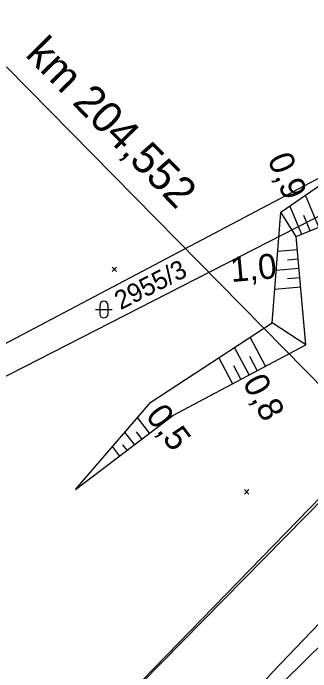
# Model space of a CAD drawing. Extents: x -800194 to -799078, y -1007177 to -1006597.
# Drawn here: x -799466.4 to -799442.5, y -1006906.1 to -1006853.3 of the extents above; entities that cross this region are included whole.
import ezdxf

# ---------------------------------------------------------------- set-up
doc = ezdxf.new("R2010")
doc.units = 0
for name, color, linetype in [('Obvod stavby', 7, 'Continuous'), ('Vrstva 4', 7, 'Continuous'), ('Vrstva 48', 7, 'Continuous'), ('Vrstva 49', 7, 'Continuous'), ('Vrstva 5', 7, 'Continuous'), ('Vrstva 53', 7, 'Continuous'), ('Vrstva 55', 7, 'Continuous'), ('Vrstva 57', 7, 'Continuous'), ('Vrstva 58', 7, 'Continuous')]:
    doc.layers.add(name, color=color, linetype=linetype)

msp = doc.modelspace()

# ---------------------------------------------------------------- linework, layer by layer
at = {"layer": 'Obvod stavby'}
msp.add_lwpolyline([(-799559.64, -1006968.48), (-799519.68, -1006952.01), (-799500.87, -1006940.41), (-799496.64, -1006937.8), (-799494.85, -1006936.7), (-799484.52, -1006930.32), (-799457.99, -1006908.8), (-799435, -1006885.17), (-799430.26, -1006880.27), (-799425.53, -1006875.38), (-799422.55, -1006864.36), (-799416.748, -1006858.798), (-799395.763, -1006879.374), (-799413.75, -1006898.23), (-799418.41, -1006902.53), (-799423.07, -1006906.83), (-799433.4, -1006916.39), (-799469.5, -1006946.86), (-799487.22, -1006958.47), (-799495.25, -1006963.74), (-799521.98, -1006977.8), (-799546.71, -1006987.83)], dxfattribs=at)
at = {"layer": 'Vrstva 4'}
msp.add_lwpolyline([(-799511.236, -1006957.129), (-799499.236, -1006950.771), (-799498.598, -1006949.914), (-799498.679, -1006949.705), (-799496.151, -1006948.479), (-799496.251, -1006948.258), (-799490.687, -1006944.683), (-799490.497, -1006944.878), (-799488.249, -1006943.052), (-799488.105, -1006943.216), (-799486.269, -1006941.68), (-799478.997, -1006936.484), (-799474.568, -1006932.916), (-799474.237, -1006932.694), (-799461.519, -1006921.99), (-799452.935, -1006914.372), (-799444.695, -1006906.886), (-799436.579, -1006898.932), (-799429.629, -1006892.192), (-799429.07, -1006892.727), (-799423.479, -1006886.901), (-799416.56, -1006880.007), (-799417.085, -1006879.46), (-799415.349, -1006878.386)], dxfattribs=at)
at = {"layer": 'Vrstva 48'}
for p, q in [((-799441.897, -1006870.468), (-799442.971, -1006867.903)), ((-799443.28, -1006871.048), (-799444.235, -1006868.768)), ((-799442.588, -1006870.758), (-799443.096, -1006869.547)), ((-799443.626, -1006872.289), (-799445.215, -1006872.43)), ((-799443.56, -1006873.036), (-799444.417, -1006873.112)), ((-799443.494, -1006873.783), (-799445.333, -1006873.946)), ((-799443.427, -1006874.53), (-799444.41, -1006874.617)), ((-799443.361, -1006875.277), (-799445.451, -1006875.463)), ((-799446.183, -1006881.617), (-799447.42, -1006879.29)), ((-799447.507, -1006882.321), (-799448.681, -1006880.114)), ((-799448.832, -1006883.025), (-799449.942, -1006880.937)), ((-799446.845, -1006881.969), (-799447.448, -1006880.835)), ((-799448.169, -1006882.673), (-799448.74, -1006881.599)), ((-799455.512, -1006887.006), (-799456.472, -1006885.742)), ((-799456.707, -1006887.913), (-799457.474, -1006886.903)), ((-799456.11, -1006887.459), (-799456.541, -1006886.891)), ((-799457.902, -1006888.82), (-799458.475, -1006888.065)), ((-799457.304, -1006888.366), (-799457.639, -1006887.925))]:
    msp.add_line(p, q, dxfattribs=at)
at = {"layer": 'Vrstva 49'}
for p, q in [((-799443.72, -1006871.232), (-799444.968, -1006869.269)), ((-799458.508, -1006873.685), (-799458.154, -1006874.039)), ((-799458.508, -1006874.039), (-799458.154, -1006873.685)), ((-799442.951, -1006879.899), (-799445.66, -1006878.142)), ((-799447.872, -1006891.527), (-799447.518, -1006891.881)), ((-799447.872, -1006891.881), (-799447.518, -1006891.527))]:
    msp.add_line(p, q, dxfattribs=at)
for points in [[(-799461.444, -1006891.51), (-799455.403, -1006884.501), (-799445.66, -1006878.142), (-799444.968, -1006869.269), (-799439.353, -1006865.427)], [(-799461.444, -1006891.51), (-799453.63, -1006885.576), (-799442.951, -1006879.899), (-799443.72, -1006871.232), (-799441.503, -1006870.303)], [(-799429.125, -1006891.656), (-799433.133, -1006889.484), (-799437.572, -1006888.963), (-799439.693, -1006890.332), (-799461.15, -1006912.135), (-799487.142, -1006929.222), (-799487.006, -1006931.546), (-799490.308, -1006935.771)], [(-799490.09, -1006944.145), (-799488.194, -1006942.597), (-799488.011, -1006942.815), (-799488.011, -1006942.815), (-799486.419, -1006941.508), (-799486.269, -1006941.68), (-799484.618, -1006939.109), (-799474.926, -1006932.405), (-799474.596, -1006932.171), (-799461.519, -1006921.99), (-799452.935, -1006914.372), (-799445.566, -1006906.106), (-799432.588, -1006892.596), (-799429.125, -1006891.656)]]:
    msp.add_lwpolyline(points, dxfattribs=at)
at = {"layer": 'Vrstva 5'}
msp.add_line((-799466.989, -1006857.616), (-799431.886, -1006893.222), dxfattribs=at)
at = {"layer": 'Vrstva 53'}
msp.add_lwpolyline([(-799559.64, -1006968.48), (-799519.68, -1006952.01), (-799500.87, -1006940.41), (-799496.64, -1006937.8), (-799494.85, -1006936.7), (-799484.519, -1006930.319), (-799457.99, -1006908.8), (-799435, -1006885.17), (-799430.26, -1006880.27), (-799425.53, -1006875.38), (-799422.55, -1006864.36), (-799390.88, -1006834), (-799358.35, -1006806.65), (-799352.29, -1006801.56), (-799330.91, -1006783.58), (-799314.235, -1006766.649)], dxfattribs=at)
at = {"layer": 'Vrstva 55'}
for points in [[(-799498.58, -1006896.8), (-799468.62, -1006880.61), (-799439.23, -1006865.13)], [(-799439.06, -1006868.14), (-799466.75, -1006882.3), (-799482.8, -1006890.48), (-799499.57, -1006898.99), (-799506.49, -1006901.85)], [(-799494.85, -1006936.7), (-799484.52, -1006930.32), (-799457.99, -1006908.8), (-799435, -1006885.17)]]:
    msp.add_lwpolyline(points, dxfattribs=at)
at = {"layer": 'Vrstva 58'}
for p, q in [((-799459.831, -1006877.081), (-799458.489, -1006877.081)), ((-799459.495, -1006876.745), (-799459.495, -1006877.416)), ((-799458.825, -1006877.416), (-799458.825, -1006876.745))]:
    msp.add_line(p, q, dxfattribs=at)
for centre, start, end in [((-799459.16, -1006876.746), 0, 180), ((-799459.16, -1006877.416), 180, 359.9879)]:
    msp.add_arc(centre, 0.335, start, end, dxfattribs=at)

# ---------------------------------------------------------------- texts
at = {"layer": 'Vrstva 48'}
for s, rotation, p in [('0,9', 292.7354, (-799446.054, -1006865.002)), ('1,0', 5.0704, (-799448.924, -1006874.881)), ('0,8', 297.9953, (-799448.066, -1006882.927)), ('0,5', 307.2133, (-799455.873, -1006885.628))]:
    msp.add_text(s, height=2, rotation=rotation, dxfattribs=at).set_placement(p)
at = {"layer": 'Vrstva 5'}
msp.add_text('km 204,552', height=2.5, rotation=314.5927, dxfattribs=at).set_placement((-799465.555, -1006856.698))
at = {"layer": 'Vrstva 57'}
msp.add_text('2955/3', height=1.5, rotation=27, dxfattribs=at).set_placement((-799457.82, -1006877.138))

doc.saveas('drawing.dxf')
